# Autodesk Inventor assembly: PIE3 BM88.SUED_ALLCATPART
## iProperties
Shininess: 64.0
Length Units: 11269
Angle Units: 11279
Time Units: 11290
Mass Units: 11286
Length Display Precision: 3
Angle Display Precision: 2
Compacted: True
Part Number: PIE3 BM88.SUED_ALLCATPART
Document SubType Name: Assembly
Created: 2004-08
Designer: John Blackburn
Manufacturer: Standard
Standards Organization: Custom
Density: 0.0
Volumn: 0.0
Area: 0.0
PropertySet Name: Model Information
Control State: 0
Master: False
Checked Out: False
Author: John Blackburn
